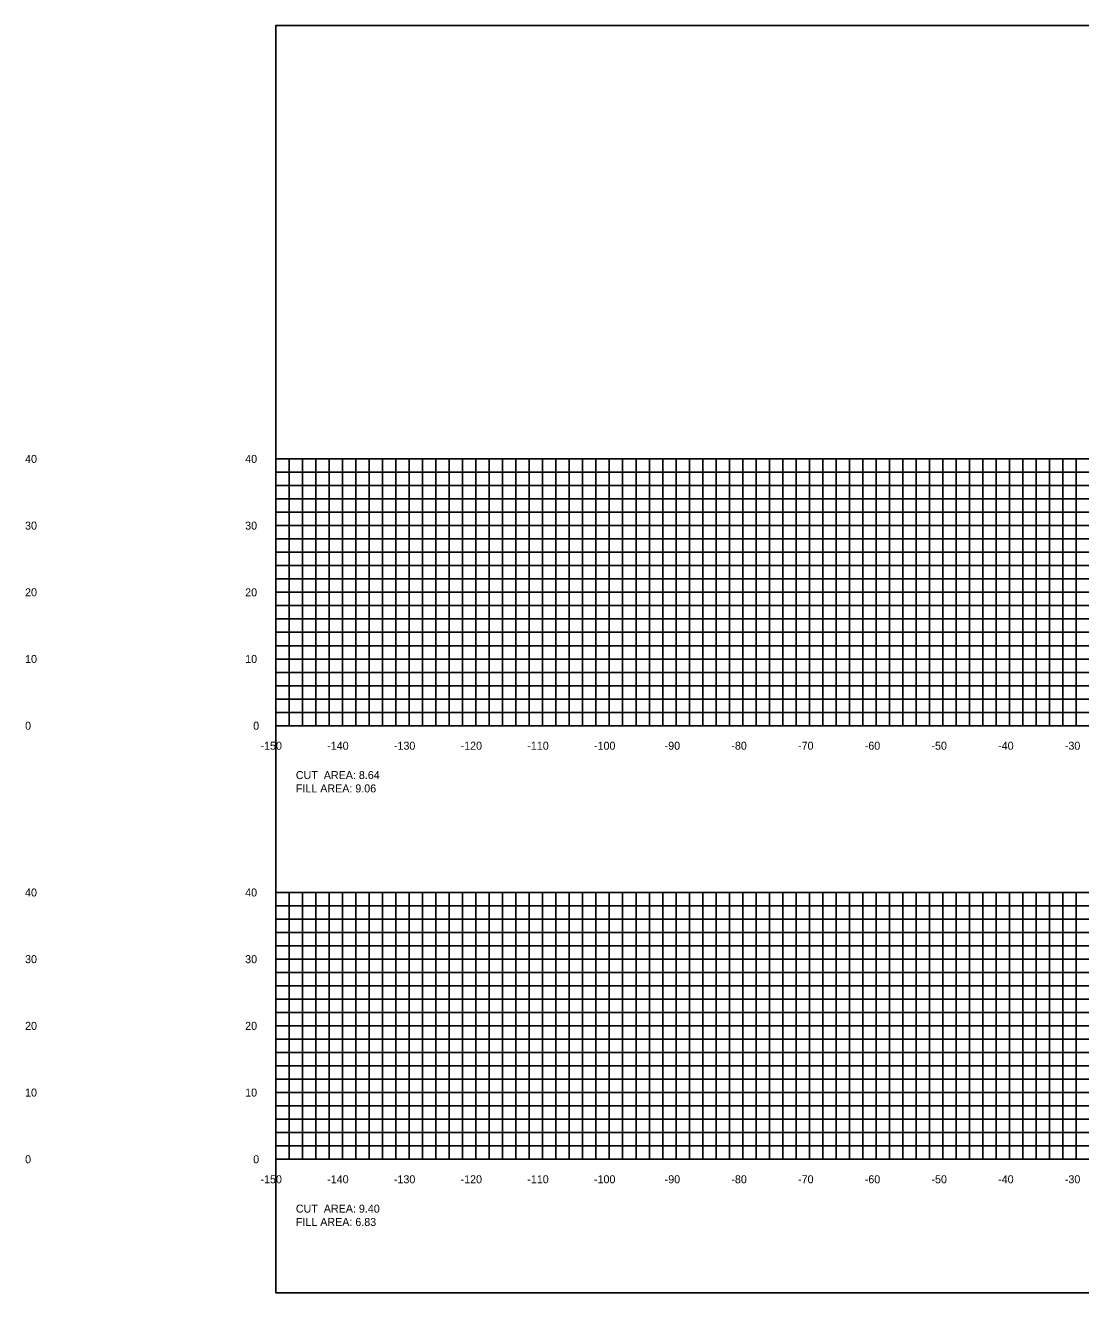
# Model space of a CAD drawing. Extents: x 1797645 to 1803805, y 248417 to 250269.
# Drawn here: x 1803123.4 to 1803281.7, y 250079.4 to 250269.4 of the extents above; entities that cross this region are included whole.
import ezdxf

# ---------------------------------------------------------------- set-up
doc = ezdxf.new("R2010")
doc.units = 0
for name, color, linetype in [('10', 7, 'Continuous'), ('31', 7, 'Continuous'), ('60', 7, 'Continuous'), ('ANNO-TXT', 7, 'Continuous'), ('Level 62', 7, 'Continuous')]:
    doc.layers.add(name, color=color, linetype=linetype)

msp = doc.modelspace()

# ---------------------------------------------------------------- linework, layer by layer
msp.add_lwpolyline([(1803161, 250079.43), (1803461, 250079.43), (1803461, 250269.43), (1803161, 250269.43)], close=True)
at = {"layer": '60'}
for p, q in [((1803160.94, 250204.43), (1803161, 250204.43)), ((1803161, 250164.43), (1803161, 250204.43)), ((1803160.94, 250194.43), (1803161, 250194.43)), ((1803160.94, 250184.43), (1803161, 250184.43)), ((1803160.94, 250174.43), (1803161, 250174.43)), ((1803160.94, 250164.43), (1803161, 250164.43)), ((1803161, 250164.43), (1803461, 250164.43)), ((1803161, 250164.37), (1803161, 250164.43)), ((1803171, 250164.37), (1803171, 250164.43)), ((1803181, 250164.37), (1803181, 250164.43)), ((1803191, 250164.37), (1803191, 250164.43)), ((1803201, 250164.37), (1803201, 250164.43)), ((1803211, 250164.37), (1803211, 250164.43)), ((1803221, 250164.37), (1803221, 250164.43)), ((1803231, 250164.37), (1803231, 250164.43)), ((1803241, 250164.37), (1803241, 250164.43)), ((1803251, 250164.37), (1803251, 250164.43)), ((1803261, 250164.37), (1803261, 250164.43)), ((1803271, 250164.37), (1803271, 250164.43)), ((1803281, 250164.37), (1803281, 250164.43)), ((1803160.94, 250139.43), (1803161, 250139.43)), ((1803161, 250099.43), (1803161, 250139.43)), ((1803160.94, 250129.43), (1803161, 250129.43)), ((1803160.94, 250119.43), (1803161, 250119.43)), ((1803160.94, 250109.43), (1803161, 250109.43)), ((1803160.94, 250099.43), (1803161, 250099.43)), ((1803161, 250099.43), (1803461, 250099.43)), ((1803161, 250099.37), (1803161, 250099.43)), ((1803171, 250099.37), (1803171, 250099.43)), ((1803181, 250099.37), (1803181, 250099.43)), ((1803191, 250099.37), (1803191, 250099.43)), ((1803201, 250099.37), (1803201, 250099.43)), ((1803211, 250099.37), (1803211, 250099.43)), ((1803221, 250099.37), (1803221, 250099.43)), ((1803231, 250099.37), (1803231, 250099.43)), ((1803241, 250099.37), (1803241, 250099.43)), ((1803251, 250099.37), (1803251, 250099.43)), ((1803261, 250099.37), (1803261, 250099.43)), ((1803271, 250099.37), (1803271, 250099.43)), ((1803281, 250099.37), (1803281, 250099.43))]:
    msp.add_line(p, q, dxfattribs=at)
at = {"layer": 'Level 62'}
for p, q in [((1803161, 250204.43), (1803461, 250204.43)), ((1803161, 250164.43), (1803161, 250204.43)), ((1803163, 250164.43), (1803163, 250204.43)), ((1803165, 250164.43), (1803165, 250204.43)), ((1803167, 250164.43), (1803167, 250204.43)), ((1803169, 250164.43), (1803169, 250204.43)), ((1803171, 250164.43), (1803171, 250204.43)), ((1803173, 250164.43), (1803173, 250204.43)), ((1803175, 250164.43), (1803175, 250204.43)), ((1803177, 250164.43), (1803177, 250204.43)), ((1803179, 250164.43), (1803179, 250204.43)), ((1803181, 250164.43), (1803181, 250204.43)), ((1803183, 250164.43), (1803183, 250204.43)), ((1803185, 250164.43), (1803185, 250204.43)), ((1803187, 250164.43), (1803187, 250204.43)), ((1803189, 250164.43), (1803189, 250204.43)), ((1803191, 250164.43), (1803191, 250204.43)), ((1803193, 250164.43), (1803193, 250204.43)), ((1803195, 250164.43), (1803195, 250204.43)), ((1803197, 250164.43), (1803197, 250204.43)), ((1803199, 250164.43), (1803199, 250204.43)), ((1803201, 250164.43), (1803201, 250204.43)), ((1803203, 250164.43), (1803203, 250204.43)), ((1803205, 250164.43), (1803205, 250204.43)), ((1803207, 250164.43), (1803207, 250204.43)), ((1803209, 250164.43), (1803209, 250204.43)), ((1803211, 250164.43), (1803211, 250204.43)), ((1803213, 250164.43), (1803213, 250204.43)), ((1803215, 250164.43), (1803215, 250204.43)), ((1803217, 250164.43), (1803217, 250204.43)), ((1803219, 250164.43), (1803219, 250204.43)), ((1803221, 250164.43), (1803221, 250204.43)), ((1803223, 250164.43), (1803223, 250204.43)), ((1803225, 250164.43), (1803225, 250204.43)), ((1803227, 250164.43), (1803227, 250204.43)), ((1803229, 250164.43), (1803229, 250204.43)), ((1803231, 250164.43), (1803231, 250204.43)), ((1803233, 250164.43), (1803233, 250204.43)), ((1803235, 250164.43), (1803235, 250204.43)), ((1803237, 250164.43), (1803237, 250204.43)), ((1803239, 250164.43), (1803239, 250204.43)), ((1803241, 250164.43), (1803241, 250204.43)), ((1803243, 250164.43), (1803243, 250204.43)), ((1803245, 250164.43), (1803245, 250204.43)), ((1803247, 250164.43), (1803247, 250204.43)), ((1803249, 250164.43), (1803249, 250204.43)), ((1803251, 250164.43), (1803251, 250204.43)), ((1803253, 250164.43), (1803253, 250204.43)), ((1803255, 250164.43), (1803255, 250204.43)), ((1803257, 250164.43), (1803257, 250204.43)), ((1803259, 250164.43), (1803259, 250204.43)), ((1803261, 250164.43), (1803261, 250204.43)), ((1803263, 250164.43), (1803263, 250204.43)), ((1803265, 250164.43), (1803265, 250204.43)), ((1803267, 250164.43), (1803267, 250204.43)), ((1803269, 250164.43), (1803269, 250204.43)), ((1803271, 250164.43), (1803271, 250204.43)), ((1803273, 250164.43), (1803273, 250204.43)), ((1803275, 250164.43), (1803275, 250204.43)), ((1803277, 250164.43), (1803277, 250204.43)), ((1803279, 250164.43), (1803279, 250204.43)), ((1803281, 250164.43), (1803281, 250204.43)), ((1803161, 250202.43), (1803461, 250202.43)), ((1803161, 250200.43), (1803461, 250200.43)), ((1803161, 250198.43), (1803461, 250198.43)), ((1803161, 250196.43), (1803461, 250196.43)), ((1803161, 250194.43), (1803461, 250194.43)), ((1803161, 250192.43), (1803461, 250192.43)), ((1803161, 250190.43), (1803461, 250190.43)), ((1803161, 250188.43), (1803461, 250188.43)), ((1803161, 250186.43), (1803461, 250186.43)), ((1803161, 250184.43), (1803461, 250184.43)), ((1803161, 250182.43), (1803461, 250182.43)), ((1803161, 250180.43), (1803461, 250180.43)), ((1803161, 250178.43), (1803461, 250178.43)), ((1803161, 250176.43), (1803461, 250176.43)), ((1803161, 250174.43), (1803461, 250174.43)), ((1803161, 250172.43), (1803461, 250172.43)), ((1803161, 250170.43), (1803461, 250170.43)), ((1803161, 250168.43), (1803461, 250168.43)), ((1803161, 250166.43), (1803461, 250166.43)), ((1803161, 250164.43), (1803461, 250164.43)), ((1803161, 250139.43), (1803461, 250139.43)), ((1803161, 250099.43), (1803161, 250139.43)), ((1803163, 250099.43), (1803163, 250139.43)), ((1803165, 250099.43), (1803165, 250139.43)), ((1803167, 250099.43), (1803167, 250139.43)), ((1803169, 250099.43), (1803169, 250139.43)), ((1803171, 250099.43), (1803171, 250139.43)), ((1803173, 250099.43), (1803173, 250139.43)), ((1803175, 250099.43), (1803175, 250139.43)), ((1803177, 250099.43), (1803177, 250139.43)), ((1803179, 250099.43), (1803179, 250139.43)), ((1803181, 250099.43), (1803181, 250139.43)), ((1803183, 250099.43), (1803183, 250139.43)), ((1803185, 250099.43), (1803185, 250139.43)), ((1803187, 250099.43), (1803187, 250139.43)), ((1803189, 250099.43), (1803189, 250139.43)), ((1803191, 250099.43), (1803191, 250139.43)), ((1803193, 250099.43), (1803193, 250139.43)), ((1803195, 250099.43), (1803195, 250139.43)), ((1803197, 250099.43), (1803197, 250139.43)), ((1803199, 250099.43), (1803199, 250139.43)), ((1803201, 250099.43), (1803201, 250139.43)), ((1803203, 250099.43), (1803203, 250139.43)), ((1803205, 250099.43), (1803205, 250139.43)), ((1803207, 250099.43), (1803207, 250139.43)), ((1803209, 250099.43), (1803209, 250139.43)), ((1803211, 250099.43), (1803211, 250139.43)), ((1803213, 250099.43), (1803213, 250139.43)), ((1803215, 250099.43), (1803215, 250139.43)), ((1803217, 250099.43), (1803217, 250139.43)), ((1803219, 250099.43), (1803219, 250139.43)), ((1803221, 250099.43), (1803221, 250139.43)), ((1803223, 250099.43), (1803223, 250139.43)), ((1803225, 250099.43), (1803225, 250139.43)), ((1803227, 250099.43), (1803227, 250139.43)), ((1803229, 250099.43), (1803229, 250139.43)), ((1803231, 250099.43), (1803231, 250139.43)), ((1803233, 250099.43), (1803233, 250139.43)), ((1803235, 250099.43), (1803235, 250139.43)), ((1803237, 250099.43), (1803237, 250139.43)), ((1803239, 250099.43), (1803239, 250139.43)), ((1803241, 250099.43), (1803241, 250139.43)), ((1803243, 250099.43), (1803243, 250139.43)), ((1803245, 250099.43), (1803245, 250139.43)), ((1803247, 250099.43), (1803247, 250139.43)), ((1803249, 250099.43), (1803249, 250139.43)), ((1803251, 250099.43), (1803251, 250139.43)), ((1803253, 250099.43), (1803253, 250139.43)), ((1803255, 250099.43), (1803255, 250139.43)), ((1803257, 250099.43), (1803257, 250139.43)), ((1803259, 250099.43), (1803259, 250139.43)), ((1803261, 250099.43), (1803261, 250139.43)), ((1803263, 250099.43), (1803263, 250139.43)), ((1803265, 250099.43), (1803265, 250139.43)), ((1803267, 250099.43), (1803267, 250139.43)), ((1803269, 250099.43), (1803269, 250139.43)), ((1803271, 250099.43), (1803271, 250139.43)), ((1803273, 250099.43), (1803273, 250139.43)), ((1803275, 250099.43), (1803275, 250139.43)), ((1803277, 250099.43), (1803277, 250139.43)), ((1803279, 250099.43), (1803279, 250139.43)), ((1803281, 250099.43), (1803281, 250139.43)), ((1803161, 250137.43), (1803461, 250137.43)), ((1803161, 250135.43), (1803461, 250135.43)), ((1803161, 250133.43), (1803461, 250133.43)), ((1803161, 250131.43), (1803461, 250131.43)), ((1803161, 250129.43), (1803461, 250129.43)), ((1803161, 250127.43), (1803461, 250127.43)), ((1803161, 250125.43), (1803461, 250125.43)), ((1803161, 250123.43), (1803461, 250123.43)), ((1803161, 250121.43), (1803461, 250121.43)), ((1803161, 250119.43), (1803461, 250119.43)), ((1803161, 250117.43), (1803461, 250117.43)), ((1803161, 250115.43), (1803461, 250115.43)), ((1803161, 250113.43), (1803461, 250113.43)), ((1803161, 250111.43), (1803461, 250111.43)), ((1803161, 250109.43), (1803461, 250109.43)), ((1803161, 250107.43), (1803461, 250107.43)), ((1803161, 250105.43), (1803461, 250105.43)), ((1803161, 250103.43), (1803461, 250103.43)), ((1803161, 250101.43), (1803461, 250101.43)), ((1803161, 250099.43), (1803461, 250099.43))]:
    msp.add_line(p, q, dxfattribs=at)

# ---------------------------------------------------------------- texts
at = {"layer": '10'}
for s, p in [('-150', (1803158.7, 250160.83)), ('-140', (1803168.7, 250160.83)), ('-130', (1803178.7, 250160.83)), ('-120', (1803188.7, 250160.83)), ('-110', (1803198.7, 250160.83)), ('-100', (1803208.7, 250160.83)), ('-90', (1803219.3, 250160.83)), ('-80', (1803229.3, 250160.83)), ('-70', (1803239.3, 250160.83)), ('-60', (1803249.3, 250160.83)), ('-50', (1803259.3, 250160.83)), ('-40', (1803269.3, 250160.83)), ('-30', (1803279.3, 250160.83)), ('-150', (1803158.7, 250095.83)), ('-140', (1803168.7, 250095.83)), ('-130', (1803178.7, 250095.83)), ('-120', (1803188.7, 250095.83)), ('-110', (1803198.7, 250095.83)), ('-100', (1803208.7, 250095.83)), ('-90', (1803219.3, 250095.83)), ('-80', (1803229.3, 250095.83)), ('-70', (1803239.3, 250095.83)), ('-60', (1803249.3, 250095.83)), ('-50', (1803259.3, 250095.83)), ('-40', (1803269.3, 250095.83)), ('-30', (1803279.3, 250095.83))]:
    msp.add_text(s, height=1.2, dxfattribs=at).set_placement(p)
at = {"layer": '31'}
for s, p in [('40', (1803123.4, 250203.83)), ('40', (1803156.4, 250203.83)), ('30', (1803123.4, 250193.83)), ('30', (1803156.4, 250193.83)), ('20', (1803123.4, 250183.83)), ('20', (1803156.4, 250183.83)), ('10', (1803123.4, 250173.83)), ('10', (1803156.4, 250173.83)), ('0', (1803123.4, 250163.83)), ('0', (1803157.6, 250163.83)), ('40', (1803123.4, 250138.83)), ('40', (1803156.4, 250138.83)), ('30', (1803123.4, 250128.83)), ('30', (1803156.4, 250128.83)), ('20', (1803123.4, 250118.83)), ('20', (1803156.4, 250118.83)), ('10', (1803123.4, 250108.83)), ('10', (1803156.4, 250108.83)), ('0', (1803123.4, 250098.83)), ('0', (1803157.6, 250098.83))]:
    msp.add_text(s, height=1.2, dxfattribs=at).set_placement(p)
at = {"layer": '60'}
for p in [(1803161, 250164.43), (1803161, 250099.43)]:
    msp.add_text('-', height=0.0001, dxfattribs=at).set_placement(p)
at = {"layer": 'ANNO-TXT'}
for s, p in [('CUT  AREA: 8.64', (1803164, 250156.43)), ('FILL AREA: 9.06', (1803164, 250154.43)), ('CUT  AREA: 9.40', (1803164, 250091.43)), ('FILL AREA: 6.83', (1803164, 250089.43))]:
    msp.add_text(s, height=1.2, dxfattribs=at).set_placement(p)

doc.saveas('drawing.dxf')
